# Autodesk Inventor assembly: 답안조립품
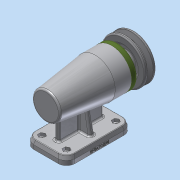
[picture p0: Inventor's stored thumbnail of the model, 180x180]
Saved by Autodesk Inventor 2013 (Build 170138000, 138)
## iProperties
Created: 2017-01
Part Number: 답안조립품
Document SubType Name: Assembly
Designer: dgall
Author: dgall
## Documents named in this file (11)
- C:\Users\dgall\Desktop\470107V1016\답안조립품.iam
- C:\Users\dgall\Desktop\470107V1016\본체.ipt
- C:\Users\dgall\Desktop\470107V1016\V벨트풀리.ipt
- C:\Users\dgall\Desktop\470107V1016\베어링 6004.ipt
- C:\Users\dgall\Desktop\470107V1016\베어링 51202.ipt
- C:\Users\dgall\Desktop\470107V1016\볼트 M4 x 12.ipt
- C:\Users\dgall\Desktop\470107V1016\어댑터슬리브.ipt
- C:\Users\dgall\Desktop\470107V1016\오일 실.ipt
- C:\Users\dgall\Desktop\470107V1016\축.ipt
- C:\Users\dgall\Desktop\470107V1016\커버.ipt
- C:\Users\dgall\Desktop\470107V1016\키 5 x 5 x 16.ipt
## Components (5 placed, 2 different names)
1. V벨트풀리:1
2. ISO 4762 M4 x 12:1
3. ISO 4762 M4 x 12:2
4. ISO 4762 M4 x 12:3
5. ISO 4762 M4 x 12:5
